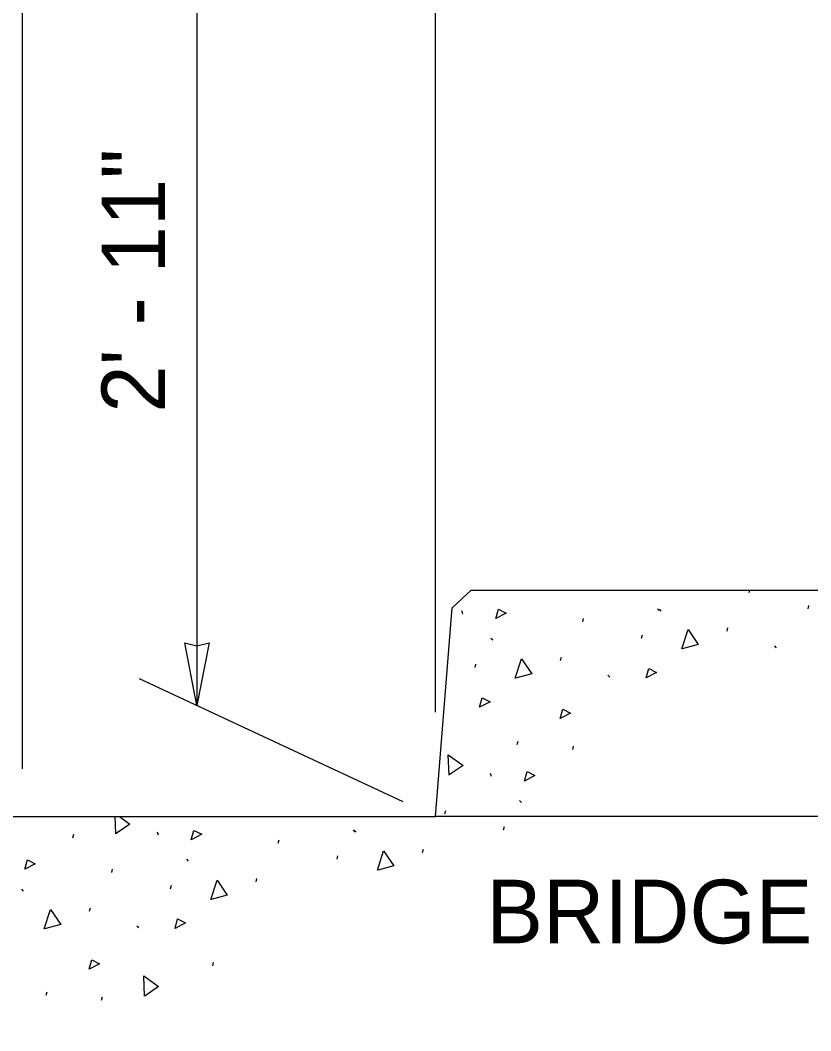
# Model space of a CAD drawing. Extents: x 36116 to 262144, y 33986 to 262144.
# Drawn here: x 100030.1 to 100228.9, y 100173.2 to 100427.4 of the extents above; entities that cross this region are included whole.
import ezdxf

# ---------------------------------------------------------------- set-up
doc = ezdxf.new("R2010")
doc.units = 0
for name, color, linetype in [('Level 14', 7, 'Continuous'), ('Level 15', 7, 'Continuous'), ('Level 17', 7, 'Continuous'), ('Level 19', 7, 'Continuous'), ('Level 20', 7, 'Continuous'), ('Level 4', 7, 'Continuous'), ('Level 5', 7, 'Continuous')]:
    doc.layers.add(name, color=color, linetype=linetype)

msp = doc.modelspace()

# ---------------------------------------------------------------- linework, layer by layer
at = {"layer": 'Level 14'}
msp.add_line((99996.11, 100227.05), (100134.51, 100227.05), dxfattribs=at)
at = {"layer": 'Level 15'}
for p, q in [((100134.51, 100253.31), (100134.51, 100559.05)), ((100074.51, 100465.03), (100074.51, 100255.03)), ((100060.01, 100261.79), (100126.28, 100230.89))]:
    msp.add_line(p, q, dxfattribs=at)
msp.add_lwpolyline([(100074.51, 100255.03), (100071.43, 100270.75), (100074.51, 100270.03), (100077.6, 100270.75)], close=True, dxfattribs=at)
at = {"layer": 'Level 17'}
for p, q in [((100138.66, 100279.56), (100143.51, 100284.05)), ((100143.51, 100284.05), (100350.51, 100284.05)), ((100134.51, 100227.05), (100138.66, 100279.56)), ((100380.51, 100227.05), (100134.51, 100227.05))]:
    msp.add_line(p, q, dxfattribs=at)
at = {"layer": 'Level 19'}
for p, q in [((100213.43, 100283.42), (100213.59, 100284.05)), ((100228.22, 100279.34), (100228.43, 100280.19)), ((100141.08, 100278.86), (100141.31, 100278.08)), ((100171.54, 100276.03), (100171.75, 100276.88)), ((100190.34, 100279.35), (100190.79, 100278.88)), ((100190.73, 100279.21), (100191.17, 100278.75)), ((100207.85, 100273.67), (100208.06, 100274.52)), ((100148.45, 100271.96), (100148.9, 100271.5)), ((100186.33, 100271.95), (100186.54, 100272.8)), ((100219.77, 100270.01), (100220.21, 100269.54)), ((100165.96, 100266.29), (100166.17, 100267.14)), ((100144.44, 100264.57), (100144.65, 100265.42)), ((100177.87, 100262.62), (100178.32, 100262.16)), ((100155.07, 100245.16), (100155.28, 100246.01)), ((100169, 100243.92), (100169.21, 100244.77)), ((100148.29, 100238), (100148.51, 100237.23)), ((100155.66, 100231.11), (100156.1, 100230.65)), ((100136.85, 100227.79), (100137.06, 100228.64)), ((100113.77, 100223.72), (100114.21, 100223.26)), ((100114.15, 100223.58), (100114.59, 100223.12)), ((100151.64, 100223.72), (100151.85, 100224.57)), ((100043.32, 100221.76), (100043.54, 100222.61)), ((100064.5, 100223.23), (100064.73, 100222.46)), ((100094.96, 100220.41), (100095.17, 100221.26)), ((100131.27, 100218.05), (100131.48, 100218.9)), ((100071.87, 100216.34), (100072.32, 100215.87)), ((100109.75, 100216.33), (100109.96, 100217.18)), ((100053.07, 100213.02), (100053.28, 100213.87)), ((100089.38, 100210.66), (100089.59, 100211.51)), ((100030.37, 100208.81), (100030.81, 100208.35)), ((100067.86, 100208.94), (100068.07, 100209.79)), ((100047.49, 100203.28), (100047.7, 100204.13)), ((100059.4, 100199.61), (100059.85, 100199.14)), ((100078.49, 100189.54), (100078.7, 100190.39)), ((100036.6, 100182.15), (100036.81, 100183)), ((100050.53, 100180.91), (100050.74, 100181.76))]:
    msp.add_line(p, q, dxfattribs=at)
for points in [[(100149.66, 100276.86), (100150.33, 100279.23), (100152.31, 100278.23), (100149.66, 100276.86)], [(100196.46, 100269.23), (100198.03, 100274.11), (100200.59, 100270.32), (100196.54, 100269.25)], [(100154.57, 100261.85), (100156.14, 100266.72), (100158.7, 100262.94), (100154.65, 100261.86)], [(100187.46, 100261.96), (100188.12, 100264.34), (100190.1, 100263.33), (100187.46, 100261.96)], [(100145.57, 100254.58), (100146.23, 100256.95), (100148.21, 100255.95), (100145.57, 100254.58)], [(100165.84, 100251.71), (100166.5, 100254.08), (100168.48, 100253.07), (100165.84, 100251.71)], [(100137.91, 100237.51), (100137.72, 100242.63), (100141.42, 100239.94), (100137.98, 100237.55)], [(100156.87, 100236.01), (100157.53, 100238.38), (100159.51, 100237.38), (100156.87, 100236.01)], [(100054.12, 100222.73), (100053.96, 100227.05)], [(100055.04, 100227.05), (100057.64, 100225.17), (100054.2, 100222.78)], [(100073.08, 100221.24), (100073.75, 100223.61), (100075.73, 100222.61), (100073.08, 100221.24)], [(100119.88, 100213.61), (100121.45, 100218.48), (100124.01, 100214.7), (100119.97, 100213.62)], [(100031.19, 100213.85), (100031.86, 100216.22), (100033.84, 100215.22), (100031.19, 100213.85)], [(100077.99, 100206.22), (100079.56, 100211.1), (100082.12, 100207.31), (100078.07, 100206.24)], [(100036.1, 100198.83), (100037.67, 100203.71), (100040.23, 100199.92), (100036.18, 100198.85)], [(100068.99, 100198.95), (100069.65, 100201.32), (100071.63, 100200.32), (100068.99, 100198.95)], [(100047.37, 100188.7), (100048.03, 100191.07), (100050.01, 100190.06), (100047.37, 100188.7)], [(100061.33, 100181.88), (100061.14, 100187), (100064.84, 100184.32), (100061.4, 100181.93)]]:
    msp.add_lwpolyline(points, dxfattribs=at)
at = {"layer": 'Level 4'}
msp.add_line((100030.51, 100617.36), (100030.51, 100239.05), dxfattribs=at)
at = {"layer": 'Level 5'}
msp.add_spline([(102147.43, 100634.59), (102161.82, 100639.44), (102158.74, 100645.43), (102162.73, 100648.51), (102160.91, 100653.23), (102160.91, 100653.23), (102154.44, 100663.63)], degree=3, dxfattribs=at)

# ---------------------------------------------------------------- texts
at = {"layer": 'Level 20'}
msp.add_text('2\' - 11"', height=16, rotation=90, dxfattribs=at).set_placement((100066.51, 100328.65))
msp.add_text('BRIDGE', height=16, dxfattribs=at).set_placement((100147.26, 100195.19))

doc.saveas('drawing.dxf')
